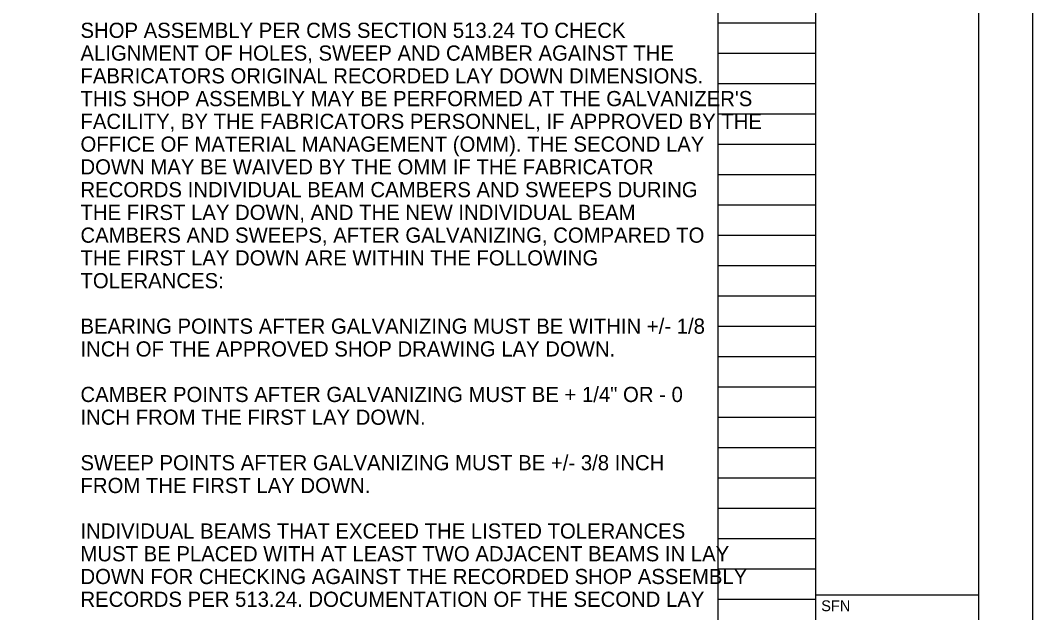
# Model space of a CAD drawing. Extents: x 0 to 45.3, y 0 to 22.
# Drawn here: x 24.66 to 34, y 5.34 to 10.8 of the extents above; entities that cross this region are included whole.
import ezdxf

# ---------------------------------------------------------------- set-up
doc = ezdxf.new("R2010")
doc.units = 0
for name, color, linetype in [('BR_P_Gen_Text', 7, 'Continuous'), ('SH_Border', 7, 'Continuous'), ('SH_Cut_Line', 7, 'Continuous'), ('SH_Data', 7, 'Continuous')]:
    doc.layers.add(name, color=color, linetype=linetype)

msp = doc.modelspace()

# ---------------------------------------------------------------- linework, layer by layer
at = {"layer": 'SH_Border'}
for p, q in [((32, 0.5), (32, 21.5)), ((32, 5.5), (33.5, 5.5))]:
    msp.add_line(p, q, dxfattribs=at)
msp.add_lwpolyline([(1.5, 21.5), (33.5, 21.5), (33.5, 0.5), (1.5, 0.5)], close=True, dxfattribs=at)
at = {"layer": 'SH_Cut_Line'}
msp.add_lwpolyline([(0, 0), (34, 0), (34, 22), (0, 22)], close=True, dxfattribs=at)
at = {"layer": 'SH_Data'}
for p, q in [((31.1, 0.98), (31.1, 21.14)), ((32, 0.98), (32, 21.14)), ((31.1, 10.78), (32, 10.78)), ((31.1, 10.5), (32, 10.5)), ((31.1, 10.22), (32, 10.22)), ((31.1, 9.94), (32, 9.94)), ((31.1, 9.66), (32, 9.66)), ((31.1, 9.38), (32, 9.38)), ((31.1, 9.1), (32, 9.1)), ((31.1, 8.82), (32, 8.82)), ((31.1, 8.54), (32, 8.54)), ((31.1, 8.26), (32, 8.26)), ((31.1, 7.98), (32, 7.98)), ((31.1, 7.7), (32, 7.7)), ((31.1, 7.42), (32, 7.42)), ((31.1, 7.14), (32, 7.14)), ((31.1, 6.86), (32, 6.86)), ((31.1, 6.58), (32, 6.58)), ((31.1, 6.3), (32, 6.3)), ((31.1, 6.02), (32, 6.02)), ((31.1, 5.74), (32, 5.74)), ((31.1, 5.46), (32, 5.46))]:
    msp.add_line(p, q, dxfattribs=at)

# ---------------------------------------------------------------- texts
at = {"layer": 'BR_P_Gen_Text'}
for s, p in [('SHOP ASSEMBLY PER CMS SECTION 513.24 TO CHECK ', (25.22, 10.64)), ('ALIGNMENT OF HOLES, SWEEP AND CAMBER AGAINST THE ', (25.22, 10.43)), ('FABRICATORS ORIGINAL RECORDED LAY DOWN DIMENSIONS. ', (25.22, 10.22)), ("THIS SHOP ASSEMBLY MAY BE PERFORMED AT THE GALVANIZER'S ", (25.22, 10.01)), ('FACILITY, BY THE FABRICATORS PERSONNEL, IF APPROVED BY THE ', (25.22, 9.8)), ('OFFICE OF MATERIAL MANAGEMENT (OMM). THE SECOND LAY ', (25.22, 9.59)), ('DOWN MAY BE WAIVED BY THE OMM IF THE FABRICATOR ', (25.22, 9.38)), ('RECORDS INDIVIDUAL BEAM CAMBERS AND SWEEPS DURING ', (25.22, 9.17)), ('THE FIRST LAY DOWN, AND THE NEW INDIVIDUAL BEAM ', (25.22, 8.96)), ('CAMBERS AND SWEEPS, AFTER GALVANIZING, COMPARED TO ', (25.22, 8.75)), ('THE FIRST LAY DOWN ARE WITHIN THE FOLLOWING ', (25.22, 8.54)), ('TOLERANCES:', (25.22, 8.33)), ('BEARING POINTS AFTER GALVANIZING MUST BE WITHIN +/- 1/8 ', (25.22, 7.91)), ('INCH OF THE APPROVED SHOP DRAWING LAY DOWN.', (25.22, 7.7)), ('CAMBER POINTS AFTER GALVANIZING MUST BE + 1/4" OR - 0 ', (25.22, 7.28)), ('INCH FROM THE FIRST LAY DOWN.', (25.22, 7.07)), ('SWEEP POINTS AFTER GALVANIZING MUST BE +/- 3/8 INCH ', (25.22, 6.65)), ('FROM THE FIRST LAY DOWN.', (25.22, 6.44)), ('INDIVIDUAL BEAMS THAT EXCEED THE LISTED TOLERANCES ', (25.22, 6.02)), ('MUST BE PLACED WITH AT LEAST TWO ADJACENT BEAMS IN LAY ', (25.22, 5.81)), ('DOWN FOR CHECKING AGAINST THE RECORDED SHOP ASSEMBLY ', (25.22, 5.6)), ('RECORDS PER 513.24. DOCUMENTATION OF THE SECOND LAY ', (25.22, 5.39))]:
    msp.add_text(s, height=0.14, dxfattribs=at).set_placement(p)
at = {"layer": 'SH_Data'}
msp.add_text('SFN', height=0.1, dxfattribs=at).set_placement((32.05, 5.35))

doc.saveas('drawing.dxf')
